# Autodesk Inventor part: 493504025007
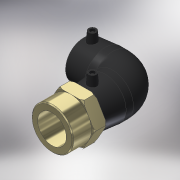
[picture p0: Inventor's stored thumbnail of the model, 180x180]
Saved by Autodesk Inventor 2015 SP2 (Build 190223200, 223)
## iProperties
Created: 2017-06
Part Number: 493504025007
Material: Generic
Description: PLASSON 90° ELBOW FEMALE TRANSITION 25-3/4''
Document SubType Name: Modeling
Designer: KIM
Mass: 78.8676 g
Surface Area: 281.357 cm^2
Volume: 78.8676 cm^3
Density: 1 g/cm^3
Appearance: Rubber - Black
Author: KIM
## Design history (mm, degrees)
derived "493504.ipt"
feature "Solid1::493504.ipt"
tag "TaggingFeature1"
body "Solid1"
other parameters: "d2" = 36, "d4" = 22, "d5" = 32.4, "d8" = 168 deg, "d10" = 14.8, "d11" = 4.93333, "d29" = 38, "d30" = 15, "d31" = 36.3, "d34" = 5 deg, "d41" = 4, "d42" = 14, "d43" = 0, "d48" = 51.3, "d49" = 25, "d50" = 21.25, "d51" = 14.8, "d52" = 37, "d54" = 90 deg, "d57" = 25, "d58" = 37, "d59" = 0, "d61" = 90 deg, "d86" = 3, "d87" = 0, "d93" = 0.1, "d96" = 24.117, "d97" = 19, "d98" = 23, "d99" = 36, "d100" = 18.4, "d107" = 9.2, "d108" = 0, "d109" = 0.75, "d112" = 45 deg, "d113" = 45 deg, "d114" = 1.25, "d_" = 25, "L_" = 89, "L_1" = 37, "D_" = 19, "A_" = 38, "d_2" = 12, "L_2" = 23, "D_1" = 36, "Rp_" = 24.117
